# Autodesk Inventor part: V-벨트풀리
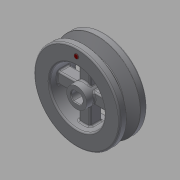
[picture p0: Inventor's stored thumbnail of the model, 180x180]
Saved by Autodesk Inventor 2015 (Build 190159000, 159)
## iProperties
Created: 2018-01
Part Number: V-벨트풀리
Material: 스테인리스강
Document SubType Name: Modeling
Designer: mduedu
Density: 8.08 g/cm^3
Appearance: 기본값
Mass: 218.724 g
Surface Area: 130.785 cm^2
Volume: 27.0698 cm^3
Author: mduedu
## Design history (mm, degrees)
sketch "스케치1"
  geometry: C1 r 30 at (0, 0); 1 further point
  constraints: 1 centre point, 1 coincident
  dimensions: "d0" = 60 diameter of C1
extrude "돌출1" new body sketch "스케치1" stored distance "d1" = 19; taper "d2" = 0 deg
sketch "스케치2"
  geometry: L1 (30, -9.5)-(-30, -9.5) reference; L2 (-30, -9.5)-(-30, 9.5) reference; L3 (-30, 9.5)-(30, 9.5) reference; L4 (30, 9.5)-(30, -9.5) reference; L5 (-30, 0)-(30, 0); L6 (30, 4.825)-(21, 2.074); L7 (21, 2.074)-(21, -2.074); L8 (21, -2.074)-(30, -4.825); L9 (30, -4.825)-(30, 4.825); L10 (27.3, 9.5)-(27.3, -9.5); L11 (0, -13.3)-(0, 13.3) reference; 4 further points
  constraints: 12 end point, 9 point on line, 3 midpoint, 2 perpendicular, 1 collinear, 1 symmetric about line
  dimensions: "d3" = 34 deg angle of L8 L6; "d4" = 2.7 distance between parallel lines of L10 L4; "d5" = 6.3 distance between parallel lines of L7 L10; "d6" = 8 distance of point (27.3, -4) point (27.3, 4)
revolve "회전1" sketch "스케치2" stored, may be unused: angle "d7" = 90 deg
fillet "모깎기1" dims "d8" = 0.2
fillet "모깎기2" dims "d9" = 0.5
fillet "모깎기3" dims "d10" = 1
sketch "스케치3"
  geometry: C1 r 19 at (0, 0); 1 further point
  constraints: 1 centre point, 1 coincident
  dimensions: "d11" = 38 diameter of C1
extrude "돌출2" cut sketch "스케치3" stored distance "d12" = 19; taper "d13" = 0 deg
sketch "스케치4"
  geometry: C1 r 7 at (0, 0); 1 further point
  constraints: 1 centre point, 1 coincident
  dimensions: "d14" = 14 diameter of C1
extrude "돌출3" join sketch "스케치4" stored distance "d15" = 19; taper "d16" = 0 deg
sketch "스케치5"
  geometry: L1 (0, 7)-(0, 19); L2 (4, 5.745)-(4, 18.574); L3 (-4, 5.745)-(-4, 18.574); C1 r 21 at (0, 0) reference; A1 r 19 centre (0, 0) between (0, 19) and (-4, 18.574) reference; A2 r 7 centre (0, 0) between (0, 7) and (-4, 5.745) reference; 1 further point
  constraints: 6 end point, 6 point on circle, 2 parallel, 1 point on line, 1 vertical, 1 other
  dimensions: "d17" = 8 distance between parallel lines of L2 L3
extrude "돌출4" join sketch "스케치5" stored distance "d18" = 8; taper "d19" = 0 deg
fillet "모깎기4" dims "d20" = 1
fillet "모깎기5" dims "d24" = 1
fillet "모깎기6" dims "d25" = 1
hole "구멍1" diameter "d28" = 8; stored, may be unused: countersink angle "d32" = 90 deg, drill point angle "d34" = 118 deg; dims "d26" = 10, "d27" = 10, "d29" = 6, "d30" = 4, "d31" = 2, "d33" = 8
sketch "스케치6"
  geometry: L1 (-2.332, -3.25)-(2.332, -3.25); L2 (2.332, 3.25)-(-2.332, 3.25); L3 (-2.332, -3.25)-(2.332, 3.25); L4 (2.332, -3.25)-(-2.332, 3.25); A1 r 4 centre (0, 0) between (2.332, 3.25) and (-2.332, 3.25) reference; A2 r 4 centre (0, 0) between (2.332, 3.25) and (-2.332, 3.25); A3 r 4 centre (0, 0) between (-2.332, -3.25) and (2.332, -3.25); 1 further point
  constraints: 8 end point, 7 point on circle, 2 centre point, 2 coincident, 2 midpoint, 1 horizontal, 1 parallel
  dimensions: "d35" = 6.5 distance of L1.end L2.start
extrude "돌출5" join sketch "스케치6" stored distance "d37" = 8; taper "d38" = 0 deg
chamfer "모따기1" distance "d39" = 0.5; stored, may be unused: second distance "d40" = 2, angle "d41" = 45 deg
chamfer "모따기2" distance "d42" = 0.5; stored, may be unused: second distance "d43" = 2, angle "d44" = 45 deg
sketch "스케치7" dims "d45" = 50
  geometry: C1 r 1.5 at (0, 25); 2 further points
  constraints: 2 vertical alignment, 1 centre point, 1 coincident, 2 other
  dimensions: "d46" = 3 diameter of C1
extrude "돌출6" join sketch "스케치7" distance "d47" = 0.5; taper "d48" = 0 deg
fillet "모깎기7" dims "d49" = 0.1
node "솔리드1"
pattern_circular "원형 패턴1" dims angle "d22" = 360 deg
node "절단 모서리 투영1"
node "절단 모서리 투영2"
